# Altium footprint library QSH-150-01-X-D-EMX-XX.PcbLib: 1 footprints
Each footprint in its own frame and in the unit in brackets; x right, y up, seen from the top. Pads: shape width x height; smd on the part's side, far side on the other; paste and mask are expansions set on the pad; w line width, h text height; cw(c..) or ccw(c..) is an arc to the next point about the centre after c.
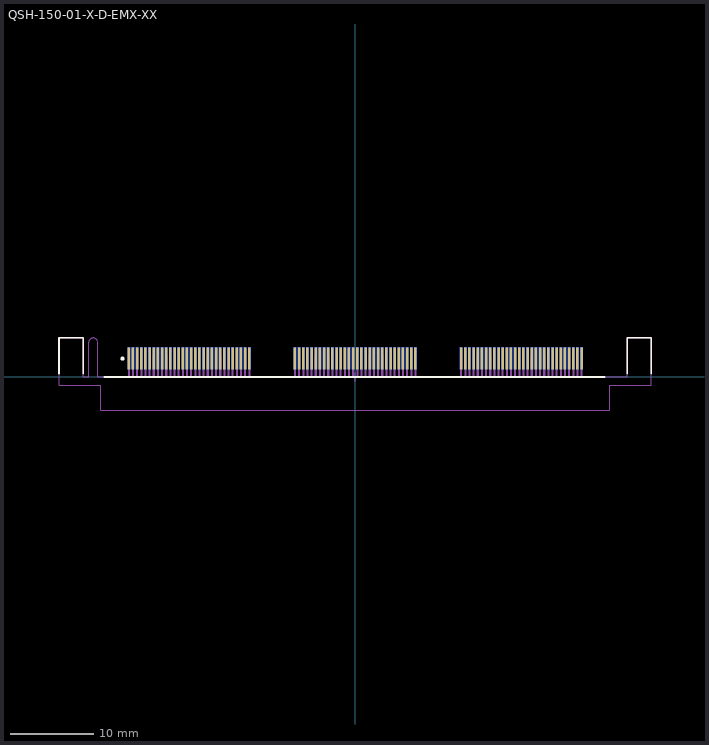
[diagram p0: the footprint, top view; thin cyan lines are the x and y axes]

## QSH-150-01-X-D-EMX-XX [mm] "0.50mm pitch, 180 pin, high speed terminal; w/edge mounts"
height 3.62
pads (180):
  rect 0.3x2.65 smd far side mask+0: 1(-27.25,2.22) 3(-26.75,2.22) 5(-26.25,2.22) 7(-25.75,2.22) 9(-25.25,2.22) 11(-24.75,2.22) 13(-24.25,2.22) 15(-23.75,2.22) 17(-23.25,2.22) 19(-22.75,2.22) 21(-22.25,2.22) 23(-21.75,2.22) 25(-21.253,2.22) 27(-20.75,2.22) 29(-20.25,2.22) 31(-19.75,2.22) 33(-19.25,2.22) 35(-18.75,2.22) 37(-18.25,2.22) 39(-17.75,2.22) 41(-17.25,2.22) 43(-16.75,2.22) 45(-16.25,2.22) 47(-15.75,2.22) 49(-15.25,2.22) 51(-14.75,2.22) 53(-14.25,2.22) 55(-13.75,2.22) 57(-13.25,2.22) 59(-12.75,2.22) 61(-7.25,2.22) 63(-6.75,2.22) 65(-6.25,2.22) 67(-5.75,2.22) 69(-5.25,2.22) 71(-4.75,2.22) 73(-4.25,2.22) 75(-3.75,2.22) 77(-3.25,2.22) 79(-2.75,2.22) 81(-2.25,2.22) 83(-1.75,2.22) 85(-1.25,2.22) 87(-0.75,2.22) 89(-0.25,2.22) 91(0.25,2.22) 93(0.75,2.22) 95(1.25,2.22) 97(1.75,2.22) 99(2.25,2.22) 101(2.75,2.22) 103(3.25,2.22) 105(3.75,2.22) 107(4.25,2.22) 109(4.75,2.22) 111(5.25,2.22) 113(5.75,2.22) 115(6.25,2.22) 117(6.75,2.22) 119(7.25,2.22) 121(12.753,2.22) 123(13.253,2.22) 125(13.753,2.22) 127(14.253,2.22) 129(14.753,2.22) 131(15.253,2.22) 133(15.753,2.22) 135(16.253,2.22) 137(16.753,2.22) 139(17.253,2.22) 141(17.753,2.22) 143(18.253,2.22) 145(18.753,2.22) 147(19.253,2.22) 149(19.753,2.22) 151(20.253,2.22) 153(20.753,2.22) 155(21.253,2.22) 157(21.753,2.22) 159(22.253,2.22) 161(22.753,2.22) 163(23.253,2.22) 165(23.753,2.22) 167(24.253,2.22) 169(24.753,2.22) 171(25.253,2.22) 173(25.753,2.22) 175(26.253,2.22) 177(26.753,2.22) 179(27.253,2.22)
  rect 0.3x2.65 smd mask+0: 2(-27.25,2.22) 4(-26.75,2.22) 6(-26.25,2.22) 8(-25.75,2.22) 10(-25.25,2.22) 12(-24.75,2.22) 14(-24.25,2.22) 16(-23.75,2.22) 18(-23.25,2.22) 20(-22.75,2.22) 22(-22.25,2.22) 24(-21.75,2.22) 26(-21.25,2.22) 28(-20.75,2.22) 30(-20.25,2.22) 32(-19.75,2.22) 34(-19.25,2.22) 36(-18.75,2.22) 38(-18.25,2.22) 40(-17.75,2.22) 42(-17.25,2.22) 44(-16.75,2.22) 46(-16.25,2.22) 48(-15.75,2.22) 50(-15.25,2.22) 52(-14.75,2.22) 54(-14.25,2.22) 56(-13.75,2.22) 58(-13.25,2.22) 60(-12.75,2.22) 62(-7.25,2.22) 64(-6.75,2.22) 66(-6.25,2.22) 68(-5.75,2.22) 70(-5.25,2.22) 72(-4.75,2.22) 74(-4.25,2.22) 76(-3.75,2.22) 78(-3.25,2.22) 80(-2.75,2.22) 82(-2.25,2.22) 84(-1.75,2.22) 86(-1.25,2.22) 88(-0.75,2.22) 90(-0.25,2.22) 92(0.25,2.22) 94(0.75,2.22) 96(1.25,2.22) 98(1.75,2.22) 100(2.25,2.22) 102(2.75,2.22) 104(3.25,2.22) 106(3.75,2.22) 108(4.25,2.22) 110(4.75,2.22) 112(5.25,2.22) 114(5.75,2.22) 116(6.25,2.22) 118(6.75,2.22) 120(7.25,2.22) 122(12.75,2.22) 124(13.25,2.22) 126(13.75,2.22) 128(14.25,2.22) 130(14.75,2.22) 132(15.25,2.22) 134(15.75,2.22) 136(16.25,2.22) 138(16.75,2.22) 140(17.25,2.22) 142(17.75,2.22) 144(18.25,2.22) 146(18.75,2.22) 148(19.25,2.22) 150(19.75,2.22) 152(20.25,2.22) 154(20.75,2.22) 156(21.25,2.22) 158(21.75,2.22) 160(22.25,2.22) 162(22.75,2.22) 164(23.25,2.22) 166(23.75,2.22) 168(24.25,2.22) 170(24.75,2.22) 172(25.25,2.22) 174(25.75,2.22) 176(26.25,2.22) 178(26.75,2.22) 180(27.25,2.22)
Top Overlay:
  circle w0.25: c-28,2.2 r0.125
  lines w0.2: -35.65,0.4 -35.65,4.7 -32.75,4.7 -32.75,0.4 ; 32.75,0.4 32.75,4.7 35.65,4.7 35.65,0.4
  lines w0.25: -30.197,0 30.003,0
Top Paste:
  lines w0.4: -30.217,0 30.003,0
Bottom Paste:
  lines w0.4: -30.217,0 30.003,0
Top Solder:
  lines w0.127: -27.25,2.184 -27.25,3.517 ; -26.75,2.184 -26.75,3.517 ; -26.25,2.184 -26.25,3.517 ; -25.75,2.184 -25.75,3.517 ; -25.25,2.184 -25.25,3.517 ; -24.75,2.184 -24.75,3.517 ; -24.25,2.184 -24.25,3.517 ; -23.75,2.184 -23.75,3.517 ; -23.25,2.184 -23.25,3.517 ; -22.75,2.184 -22.75,3.517 ; -22.25,2.184 -22.25,3.517 ; -21.75,2.184 -21.75,3.517 ; -21.25,2.184 -21.25,3.517 ; -20.75,2.184 -20.75,3.517 ; -20.25,2.184 -20.25,3.517 ; -19.75,2.184 -19.75,3.517 ; -19.25,2.184 -19.25,3.517 ; -18.75,2.184 -18.75,3.517 ; -18.25,2.184 -18.25,3.517 ; -17.75,2.184 -17.75,3.517 ; -17.25,2.184 -17.25,3.517 ; -16.75,2.184 -16.75,3.517 ; -16.25,2.184 -16.25,3.517 ; -15.75,2.184 -15.75,3.517 ; -15.25,2.184 -15.25,3.517 ; -14.75,2.184 -14.75,3.517 ; -14.25,2.184 -14.25,3.517 ; -13.75,2.184 -13.75,3.517 ; -13.25,2.184 -13.25,3.517 ; -12.75,2.184 -12.75,3.517 ; -7.25,2.184 -7.25,3.517 ; -6.75,2.184 -6.75,3.517 ; -6.25,2.184 -6.25,3.517 ; -5.75,2.184 -5.75,3.517 ; -5.25,2.184 -5.25,3.517 ; -4.75,2.184 -4.75,3.517 ; -4.25,2.184 -4.25,3.517 ; -3.75,2.184 -3.75,3.517 ; -3.25,2.184 -3.25,3.517 ; -2.75,2.184 -2.75,3.517 ; -2.25,2.184 -2.25,3.517 ; -1.75,2.184 -1.75,3.517 ; -1.25,2.184 -1.25,3.517 ; -0.75,2.184 -0.75,3.517 ; -0.25,2.184 -0.25,3.517 ; 0.25,2.184 0.25,3.517 ; 0.75,2.184 0.75,3.517 ; 1.25,2.184 1.25,3.517 ; 1.75,2.184 1.75,3.517 ; 2.25,2.184 2.25,3.517 ; 2.75,2.184 2.75,3.517 ; 3.25,2.184 3.25,3.517 ; 3.75,2.184 3.75,3.517 ; 4.25,2.184 4.25,3.517 ; 4.75,2.184 4.75,3.517 ; 5.25,2.184 5.25,3.517 ; 5.75,2.184 5.75,3.517 ; 6.25,2.184 6.25,3.517 ; 6.75,2.184 6.75,3.517 ; 7.25,2.184 7.25,3.517 ; 12.75,2.184 12.75,3.517 ; 13.25,2.184 13.25,3.517 ; 13.75,2.184 13.75,3.517 ; 14.25,2.184 14.25,3.517 ; 14.75,2.184 14.75,3.517 ; 15.25,2.184 15.25,3.517 ; 15.75,2.184 15.75,3.517 ; 16.25,2.184 16.25,3.517 ; 16.75,2.184 16.75,3.517 ; 17.25,2.184 17.25,3.517 ; 17.75,2.184 17.75,3.517 ; 18.25,2.184 18.25,3.517 ; 18.75,2.184 18.75,3.517 ; 19.25,2.184 19.25,3.517 ; 19.75,2.184 19.75,3.517 ; 20.25,2.184 20.25,3.517 ; 20.75,2.184 20.75,3.517 ; 21.25,2.184 21.25,3.517 ; 21.75,2.184 21.75,3.517 ; 22.25,2.184 22.25,3.517 ; 22.75,2.184 22.75,3.517 ; 23.25,2.184 23.25,3.517 ; 23.75,2.184 23.75,3.517 ; 24.25,2.184 24.25,3.517 ; 24.75,2.184 24.75,3.517 ; 25.25,2.184 25.25,3.517 ; 25.75,2.184 25.75,3.517 ; 26.25,2.184 26.25,3.517 ; 26.75,2.184 26.75,3.517 ; 27.25,2.184 27.25,3.517
Bottom Solder:
  lines w0.127: -27.25,2.184 -27.25,3.517 ; -26.75,2.184 -26.75,3.517 ; -26.25,2.184 -26.25,3.517 ; -25.75,2.184 -25.75,3.517 ; -25.25,2.184 -25.25,3.517 ; -24.75,2.184 -24.75,3.517 ; -24.25,2.184 -24.25,3.517 ; -23.75,2.184 -23.75,3.517 ; -23.25,2.184 -23.25,3.517 ; -22.75,2.184 -22.75,3.517 ; -22.25,2.184 -22.25,3.517 ; -21.75,2.184 -21.75,3.517 ; -21.25,2.184 -21.25,3.517 ; -20.75,2.184 -20.75,3.517 ; -20.25,2.184 -20.25,3.517 ; -19.75,2.184 -19.75,3.517 ; -19.25,2.184 -19.25,3.517 ; -18.75,2.184 -18.75,3.517 ; -18.25,2.184 -18.25,3.517 ; -17.75,2.184 -17.75,3.517 ; -17.25,2.184 -17.25,3.517 ; -16.75,2.184 -16.75,3.517 ; -16.25,2.184 -16.25,3.517 ; -15.75,2.184 -15.75,3.517 ; -15.25,2.184 -15.25,3.517 ; -14.75,2.184 -14.75,3.517 ; -14.25,2.184 -14.25,3.517 ; -13.75,2.184 -13.75,3.517 ; -13.25,2.184 -13.25,3.517 ; -12.75,2.184 -12.75,3.517 ; -7.25,2.184 -7.25,3.517 ; -6.75,2.184 -6.75,3.517 ; -6.25,2.184 -6.25,3.517 ; -5.75,2.184 -5.75,3.517 ; -5.25,2.184 -5.25,3.517 ; -4.75,2.184 -4.75,3.517 ; -4.25,2.184 -4.25,3.517 ; -3.75,2.184 -3.75,3.517 ; -3.25,2.184 -3.25,3.517 ; -2.75,2.184 -2.75,3.517 ; -2.25,2.184 -2.25,3.517 ; -1.75,2.184 -1.75,3.517 ; -1.25,2.184 -1.25,3.517 ; -0.75,2.184 -0.75,3.517 ; -0.25,2.184 -0.25,3.517 ; 0.25,2.184 0.25,3.517 ; 0.75,2.184 0.75,3.517 ; 1.25,2.184 1.25,3.517 ; 1.75,2.184 1.75,3.517 ; 2.25,2.184 2.25,3.517 ; 2.75,2.184 2.75,3.517 ; 3.25,2.184 3.25,3.517 ; 3.75,2.184 3.75,3.517 ; 4.25,2.184 4.25,3.517 ; 4.75,2.184 4.75,3.517 ; 5.25,2.184 5.25,3.517 ; 5.75,2.184 5.75,3.517 ; 6.25,2.184 6.25,3.517 ; 6.75,2.184 6.75,3.517 ; 7.25,2.184 7.25,3.517 ; 12.75,2.184 12.75,3.517 ; 13.25,2.184 13.25,3.517 ; 13.75,2.184 13.75,3.517 ; 14.25,2.184 14.25,3.517 ; 14.75,2.184 14.75,3.517 ; 15.25,2.184 15.25,3.517 ; 15.75,2.184 15.75,3.517 ; 16.25,2.184 16.25,3.517 ; 16.75,2.184 16.75,3.517 ; 17.25,2.184 17.25,3.517 ; 17.75,2.184 17.75,3.517 ; 18.25,2.184 18.25,3.517 ; 18.75,2.184 18.75,3.517 ; 19.25,2.184 19.25,3.517 ; 19.75,2.184 19.75,3.517 ; 20.25,2.184 20.25,3.517 ; 20.75,2.184 20.75,3.517 ; 21.25,2.184 21.25,3.517 ; 21.75,2.184 21.75,3.517 ; 22.25,2.184 22.25,3.517 ; 22.75,2.184 22.75,3.517 ; 23.25,2.184 23.25,3.517 ; 23.75,2.184 23.75,3.517 ; 24.25,2.184 24.25,3.517 ; 24.75,2.184 24.75,3.517 ; 25.25,2.184 25.25,3.517 ; 25.75,2.184 25.75,3.517 ; 26.25,2.184 26.25,3.517 ; 26.75,2.184 26.75,3.517 ; 27.25,2.184 27.25,3.517
Mechanical 4:
  lines w0.254: -30.217,0 30.003,0
Mechanical 13:
  lines w0.1: -35.65,-1 -30.635,-1 -30.635,-4 30.635,-4 30.635,-1 35.65,-1 35.65,4.7 32.75,4.7 32.75,0 -31,0 -31,4.15 ccw(c-31.545,4.15) -32.09,4.15 -32.09,0 -32.75,0 -32.75,4.7 -35.65,4.7 -35.65,-1
  lines w0.25: -27.25,0.003 -27.25,2.603 ; -26.75,0.003 -26.75,2.603 ; -26.25,0.003 -26.25,2.603 ; -25.75,0.003 -25.75,2.603 ; -25.25,0.003 -25.25,2.603 ; -24.75,0.003 -24.75,2.603 ; -24.25,0.003 -24.25,2.603 ; -23.75,0.003 -23.75,2.603 ; -23.25,0.003 -23.25,2.603 ; -22.75,0.003 -22.75,2.603 ; -22.25,0.003 -22.25,2.603 ; -21.75,0.003 -21.75,2.603 ; -21.25,0.003 -21.25,2.603 ; -20.75,0.003 -20.75,2.603 ; -20.25,0.003 -20.25,2.603 ; -19.75,0.003 -19.75,2.603 ; -19.25,0.003 -19.25,2.603 ; -18.75,0.003 -18.75,2.603 ; -18.25,0.003 -18.25,2.603 ; -17.75,0.003 -17.75,2.603 ; -17.25,0.003 -17.25,2.603 ; -16.75,0.003 -16.75,2.603 ; -16.25,0.003 -16.25,2.603 ; -15.75,0.003 -15.75,2.603 ; -15.25,0.003 -15.25,2.603 ; -14.75,0.003 -14.75,2.603 ; -14.25,0.003 -14.25,2.603 ; -13.75,0.003 -13.75,2.603 ; -13.25,0.003 -13.25,2.603 ; -12.75,0.003 -12.75,2.603 ; -7.25,0.003 -7.25,2.603 ; -6.75,0.003 -6.75,2.603 ; -6.25,0.003 -6.25,2.603 ; -5.75,0.003 -5.75,2.603 ; -5.25,0.003 -5.25,2.603 ; -4.75,0.003 -4.75,2.603 ; -4.25,0.003 -4.25,2.603 ; -3.75,0.003 -3.75,2.603 ; -3.25,0.003 -3.25,2.603 ; -2.75,0.003 -2.75,2.603 ; -2.25,0.003 -2.25,2.603 ; -1.75,0.003 -1.75,2.603 ; -1.25,0.003 -1.25,2.603 ; -0.75,0.003 -0.75,2.603 ; -0.25,0.003 -0.25,2.603 ; 0.25,0.003 0.25,2.603 ; 0.75,0.003 0.75,2.603 ; 1.25,0.003 1.25,2.603 ; 1.75,0.003 1.75,2.603 ; 2.25,0.003 2.25,2.603 ; 2.75,0.003 2.75,2.603 ; 3.25,0.003 3.25,2.603 ; 3.75,0.003 3.75,2.603 ; 4.25,0.003 4.25,2.603 ; 4.75,0.003 4.75,2.603 ; 5.25,0.003 5.25,2.603 ; 5.75,0.003 5.75,2.603 ; 6.25,0.003 6.25,2.603 ; 6.75,0.003 6.75,2.603 ; 7.25,0.003 7.25,2.603 ; 12.75,0.003 12.75,2.603 ; 13.25,0.003 13.25,2.603 ; 13.75,0.003 13.75,2.603 ; 14.25,0.003 14.25,2.603 ; 14.75,0.003 14.75,2.603 ; 15.25,0.003 15.25,2.603 ; 15.75,0.003 15.75,2.603 ; 16.25,0.003 16.25,2.603 ; 16.75,0.003 16.75,2.603 ; 17.25,0.003 17.25,2.603 ; 17.75,0.003 17.75,2.603 ; 18.25,0.003 18.25,2.603 ; 18.75,0.003 18.75,2.603 ; 19.25,0.003 19.25,2.603 ; 19.75,0.003 19.75,2.603 ; 20.25,0.003 20.25,2.603 ; 20.75,0.003 20.75,2.603 ; 21.25,0.003 21.25,2.603 ; 21.75,0.003 21.75,2.603 ; 22.25,0.003 22.25,2.603 ; 22.75,0.003 22.75,2.603 ; 23.25,0.003 23.25,2.603 ; 23.75,0.003 23.75,2.603 ; 24.25,0.003 24.25,2.603 ; 24.75,0.003 24.75,2.603 ; 25.25,0.003 25.25,2.603 ; 25.75,0.003 25.75,2.603 ; 26.25,0.003 26.25,2.603 ; 26.75,0.003 26.75,2.603 ; 27.25,0.003 27.25,2.603
  text ".Designator" at 0,0 h1.52
Mechanical 15:
  lines w0.05: -0.497,0 0.503,0 ; 0,-0.5 0,0.5
Drill Drawing:
  lines w0.01: -38.447,0 -32.09,0 -32.09,4.15 cw(c-31.545,4.15) -31,4.15 -31,0 38.153,0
